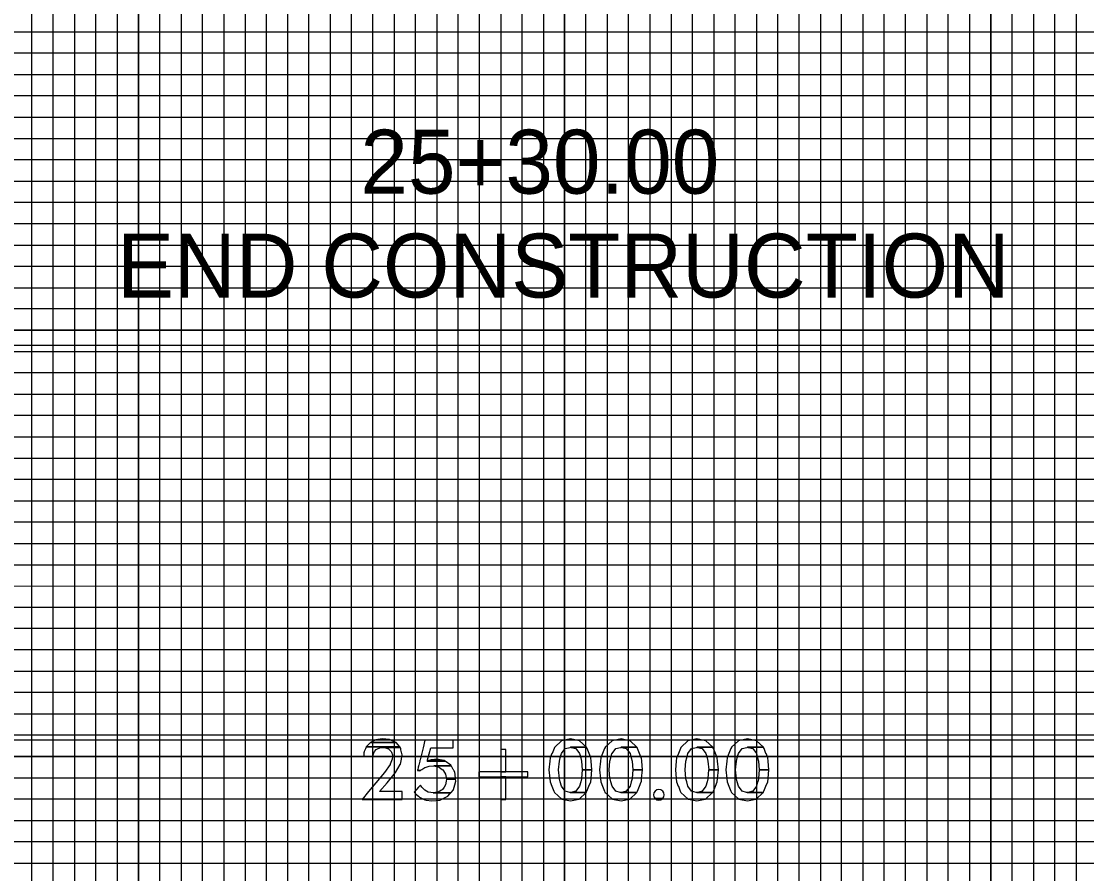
# Model space of a CAD drawing. Extents: x -13 to 323, y -5 to 1431.
# Drawn here: x 134.5 to 184.5, y 1164.5 to 1204.5 of the extents above; entities that cross this region are included whole.
import ezdxf

# ---------------------------------------------------------------- set-up
doc = ezdxf.new("R2010")
doc.units = 0
for name, color, linetype in [('Prop XS Station Labels', 7, 'Continuous'), ('Scratch_Level_3', 7, 'Continuous'), ('Scratch_Level_5', 7, 'Continuous'), ('Sheet Cross Section Grid Major CELL', 7, 'Continuous'), ('Sheet Cross Section Grid Middle CELL', 7, 'Continuous'), ('Sheet Cross Section Grid Minor 1 CELL', 7, 'Continuous'), ('Sheet Cross Section Grid Minor 2 CELL', 7, 'Continuous'), ('Sheet DOT Grid CELL', 7, 'Continuous')]:
    doc.layers.add(name, color=color, linetype=linetype)

msp = doc.modelspace()

# ---------------------------------------------------------------- linework, layer by layer
at = {"layer": 'Prop XS Station Labels'}
for points in [[(150.885, 1170.655), (150.69, 1170.447), (152.265, 1170.447), (152.085, 1170.655)], [(150.895, 1170.659), (150.885, 1170.655), (152.085, 1170.655), (152.082, 1170.659), (151.818, 1170.778), (151.786, 1170.793), (151.458, 1170.826), (151.458, 1170.826), (151.24, 1170.793), (151.144, 1170.778)], [(153.097, 1169.368), (153.092, 1169.345), (153.232, 1169.345), (153.259, 1169.368), (153.291, 1169.397), (153.433, 1169.483), (153.496, 1169.503), (153.636, 1169.546), (153.865, 1169.559), (154.681, 1169.559), (154.665, 1169.59), (154.396, 1169.78), (153.553, 1169.78), (153.56, 1169.806), (153.559, 1169.806), (153.57, 1169.845), (153.718, 1170.402), (154.769, 1170.402), (154.769, 1170.771), (153.443, 1170.771), (153.352, 1170.402), (153.215, 1169.845), (153.205, 1169.806), (153.199, 1169.78), (153.152, 1169.59), (153.145, 1169.559), (153.141, 1169.546), (153.13, 1169.503), (153.125, 1169.483), (153.105, 1169.397)], [(159.873, 1167.998), (160.272, 1167.916), (160.661, 1167.998), (160.683, 1168.003), (161.014, 1168.306), (160.265, 1168.306), (160.246, 1168.312), (160.236, 1168.315), (160.027, 1168.374), (159.853, 1168.6), (159.852, 1168.602), (159.852, 1168.602), (159.797, 1168.804), (159.796, 1168.807), (159.756, 1168.953), (159.754, 1168.962), (159.718, 1169.366), (159.718, 1169.371), (159.719, 1169.376), (159.754, 1169.779), (159.795, 1169.933), (159.796, 1169.937), (159.849, 1170.134), (159.851, 1170.14), (160.027, 1170.368), (160.253, 1170.427), (160.26, 1170.429), (160.281, 1170.435), (161.021, 1170.435), (160.695, 1170.734), (160.678, 1170.737), (160.276, 1170.826), (160.276, 1170.826), (159.86, 1170.737), (159.856, 1170.734), (159.533, 1170.435), (159.527, 1170.429), (159.525, 1170.427), (159.501, 1170.368), (159.407, 1170.14), (159.404, 1170.134), (159.324, 1169.937), (159.323, 1169.933), (159.307, 1169.779), (159.264, 1169.376), (159.264, 1169.371), (159.264, 1169.366), (159.305, 1168.962), (159.305, 1168.953), (159.32, 1168.807), (159.321, 1168.804), (159.403, 1168.602), (159.404, 1168.6), (159.496, 1168.374), (159.52, 1168.315), (159.522, 1168.312), (159.528, 1168.306), (159.867, 1168.003)], [(162.245, 1167.998), (162.645, 1167.916), (163.034, 1167.998), (163.055, 1168.003), (163.386, 1168.306), (162.638, 1168.306), (162.619, 1168.312), (162.609, 1168.315), (162.4, 1168.374), (162.225, 1168.6), (162.225, 1168.602), (162.225, 1168.602), (162.17, 1168.804), (162.169, 1168.807), (162.129, 1168.953), (162.126, 1168.962), (162.091, 1169.366), (162.091, 1169.371), (162.091, 1169.376), (162.126, 1169.779), (162.168, 1169.933), (162.169, 1169.937), (162.222, 1170.134), (162.224, 1170.14), (162.4, 1170.368), (162.625, 1170.427), (162.633, 1170.429), (162.654, 1170.435), (163.394, 1170.435), (163.067, 1170.734), (163.05, 1170.737), (162.649, 1170.826), (162.649, 1170.826), (162.233, 1170.737), (162.229, 1170.734), (161.906, 1170.435), (161.9, 1170.429), (161.898, 1170.427), (161.874, 1170.368), (161.78, 1170.14), (161.777, 1170.134), (161.696, 1169.937), (161.695, 1169.933), (161.68, 1169.779), (161.637, 1169.376), (161.636, 1169.371), (161.637, 1169.366), (161.677, 1168.962), (161.678, 1168.953), (161.693, 1168.807), (161.694, 1168.804), (161.776, 1168.602), (161.777, 1168.6), (161.869, 1168.374), (161.893, 1168.315), (161.895, 1168.312), (161.9, 1168.306), (162.24, 1168.003)], [(165.805, 1167.998), (166.204, 1167.916), (166.593, 1167.998), (166.615, 1168.003), (166.945, 1168.306), (166.197, 1168.306), (166.178, 1168.312), (166.168, 1168.315), (165.959, 1168.374), (165.785, 1168.6), (165.784, 1168.602), (165.784, 1168.602), (165.729, 1168.804), (165.728, 1168.807), (165.688, 1168.953), (165.685, 1168.962), (165.65, 1169.366), (165.65, 1169.371), (165.65, 1169.376), (165.685, 1169.779), (165.727, 1169.933), (165.728, 1169.937), (165.781, 1170.134), (165.783, 1170.14), (165.959, 1170.368), (166.185, 1170.427), (166.192, 1170.429), (166.213, 1170.435), (166.953, 1170.435), (166.626, 1170.734), (166.61, 1170.737), (166.208, 1170.826), (166.208, 1170.826), (165.792, 1170.737), (165.788, 1170.734), (165.465, 1170.435), (165.459, 1170.429), (165.457, 1170.427), (165.433, 1170.368), (165.339, 1170.14), (165.336, 1170.134), (165.255, 1169.937), (165.255, 1169.933), (165.239, 1169.779), (165.196, 1169.376), (165.195, 1169.371), (165.196, 1169.366), (165.236, 1168.962), (165.237, 1168.953), (165.252, 1168.807), (165.253, 1168.804), (165.335, 1168.602), (165.336, 1168.6), (165.428, 1168.374), (165.452, 1168.315), (165.454, 1168.312), (165.46, 1168.306), (165.799, 1168.003)], [(168.177, 1167.998), (168.576, 1167.916), (168.965, 1167.998), (168.987, 1168.003), (169.318, 1168.306), (168.57, 1168.306), (168.55, 1168.312), (168.541, 1168.315), (168.332, 1168.374), (168.157, 1168.6), (168.157, 1168.602), (168.156, 1168.602), (168.101, 1168.804), (168.1, 1168.807), (168.06, 1168.953), (168.058, 1168.962), (168.023, 1169.366), (168.023, 1169.371), (168.023, 1169.376), (168.058, 1169.779), (168.1, 1169.933), (168.1, 1169.937), (168.154, 1170.134), (168.155, 1170.14), (168.332, 1170.368), (168.557, 1170.427), (168.565, 1170.429), (168.585, 1170.435), (169.325, 1170.435), (168.999, 1170.734), (168.982, 1170.737), (168.581, 1170.826), (168.58, 1170.826), (168.165, 1170.737), (168.16, 1170.734), (167.838, 1170.435), (167.832, 1170.429), (167.83, 1170.427), (167.805, 1170.368), (167.711, 1170.14), (167.709, 1170.134), (167.628, 1169.937), (167.627, 1169.933), (167.611, 1169.779), (167.569, 1169.376), (167.568, 1169.371), (167.569, 1169.366), (167.609, 1168.962), (167.61, 1168.953), (167.625, 1168.807), (167.625, 1168.804), (167.708, 1168.602), (167.709, 1168.6), (167.801, 1168.374), (167.825, 1168.315), (167.826, 1168.312), (167.832, 1168.306), (168.172, 1168.003)], [(150.8, 1168.353), (150.496, 1167.989), (152.376, 1167.989), (152.376, 1168.353), (151.308, 1168.353), (151.667, 1168.766), (152.06, 1169.246), (152.065, 1169.251), (152.287, 1169.626), (152.286, 1169.626), (152.293, 1169.636), (152.34, 1169.876), (152.365, 1169.997), (152.375, 1170.047), (152.37, 1170.069), (152.369, 1170.075), (152.343, 1170.196), (152.34, 1170.208), (152.335, 1170.23), (152.314, 1170.332), (152.314, 1170.332), (152.308, 1170.359), (152.297, 1170.411), (152.292, 1170.416), (152.285, 1170.425), (151.548, 1170.425), (151.571, 1170.416), (151.587, 1170.411), (151.736, 1170.359), (151.763, 1170.332), (151.863, 1170.23), (151.87, 1170.208), (151.874, 1170.196), (151.915, 1170.075), (151.915, 1170.069), (151.915, 1170.047), (151.914, 1169.997), (151.912, 1169.876), (151.817, 1169.636), (151.814, 1169.626), (151.549, 1169.251), (151.545, 1169.246), (151.144, 1168.766)], [(150.569, 1170.047), (150.565, 1169.997), (151.004, 1169.997), (151.008, 1170.047), (151.01, 1170.069), (151.012, 1170.075), (151.056, 1170.196), (151.065, 1170.208), (151.082, 1170.23), (151.161, 1170.332), (151.215, 1170.359), (151.32, 1170.411), (151.331, 1170.416), (151.548, 1170.425), (152.285, 1170.425), (152.265, 1170.447), (150.69, 1170.447), (150.68, 1170.425), (150.676, 1170.416), (150.674, 1170.411), (150.65, 1170.359), (150.639, 1170.332), (150.593, 1170.23), (150.584, 1170.208), (150.582, 1170.196), (150.571, 1170.075), (150.571, 1170.069)], [(157.009, 1170.331), (157.009, 1169.274), (157.236, 1169.274), (157.236, 1170.331)], [(160.795, 1169.779), (160.827, 1169.376), (161.281, 1169.376), (161.242, 1169.779), (161.227, 1169.933), (161.225, 1169.937), (161.225, 1169.937), (161.146, 1170.134), (161.146, 1170.134), (161.144, 1170.14), (161.052, 1170.368), (161.051, 1170.368), (161.028, 1170.427), (161.027, 1170.429), (161.021, 1170.435), (160.281, 1170.435), (160.3, 1170.429), (160.307, 1170.427), (160.52, 1170.368), (160.695, 1170.14), (160.7, 1170.134), (160.752, 1169.937), (160.753, 1169.933)], [(163.167, 1169.779), (163.2, 1169.376), (163.654, 1169.376), (163.615, 1169.779), (163.6, 1169.933), (163.598, 1169.937), (163.598, 1169.937), (163.519, 1170.134), (163.519, 1170.134), (163.516, 1170.14), (163.425, 1170.368), (163.424, 1170.368), (163.4, 1170.427), (163.4, 1170.429), (163.394, 1170.435), (162.654, 1170.435), (162.673, 1170.429), (162.68, 1170.427), (162.893, 1170.368), (163.068, 1170.14), (163.073, 1170.134), (163.125, 1169.937), (163.126, 1169.933)], [(166.726, 1169.779), (166.759, 1169.376), (167.213, 1169.376), (167.174, 1169.779), (167.159, 1169.933), (167.157, 1169.937), (167.157, 1169.937), (167.078, 1170.134), (167.078, 1170.134), (167.075, 1170.14), (166.984, 1170.368), (166.983, 1170.368), (166.96, 1170.427), (166.959, 1170.429), (166.953, 1170.435), (166.213, 1170.435), (166.232, 1170.429), (166.239, 1170.427), (166.452, 1170.368), (166.627, 1170.14), (166.632, 1170.134), (166.684, 1169.937), (166.685, 1169.933)], [(169.099, 1169.779), (169.132, 1169.376), (169.586, 1169.376), (169.546, 1169.779), (169.532, 1169.933), (169.53, 1169.937), (169.53, 1169.937), (169.451, 1170.134), (169.45, 1170.134), (169.448, 1170.14), (169.356, 1170.368), (169.356, 1170.368), (169.332, 1170.427), (169.332, 1170.429), (169.325, 1170.435), (168.585, 1170.435), (168.605, 1170.429), (168.611, 1170.427), (168.825, 1170.368), (169, 1170.14), (169.005, 1170.134), (169.057, 1169.937), (169.058, 1169.933)], [(153.628, 1169.806), (153.553, 1169.78), (154.396, 1169.78), (154.36, 1169.806), (154.165, 1169.845), (153.743, 1169.845)], [(154.019, 1169.874), (153.744, 1169.845), (154.164, 1169.845), (154.019, 1169.874)], [(154.409, 1169.171), (154.454, 1168.931), (154.879, 1168.931), (154.857, 1169.171), (154.857, 1169.171), (154.85, 1169.252), (154.811, 1169.322), (154.799, 1169.345), (154.786, 1169.368), (154.77, 1169.397), (154.723, 1169.483), (154.712, 1169.503), (154.688, 1169.546), (154.681, 1169.559), (153.865, 1169.559), (153.918, 1169.546), (154.1, 1169.503), (154.128, 1169.483), (154.25, 1169.397), (154.291, 1169.368), (154.305, 1169.345), (154.319, 1169.322), (154.36, 1169.252)], [(153.091, 1169.345), (153.207, 1169.322), (153.232, 1169.345)], [(155.974, 1169.274), (155.974, 1169.046), (158.272, 1169.046), (158.272, 1169.274)], [(157.009, 1169.046), (157.009, 1167.989), (157.236, 1167.989), (157.236, 1169.046)], [(160.286, 1168.312), (160.265, 1168.306), (161.014, 1168.306), (161.02, 1168.312), (161.023, 1168.315), (161.047, 1168.374), (161.14, 1168.6), (161.141, 1168.602), (161.225, 1168.804), (161.226, 1168.807), (161.24, 1168.953), (161.241, 1168.962), (161.281, 1169.366), (161.282, 1169.371), (161.281, 1169.376), (160.827, 1169.376), (160.827, 1169.371), (160.826, 1169.366), (160.794, 1168.962), (160.794, 1168.953), (160.754, 1168.807), (160.753, 1168.804), (160.699, 1168.602), (160.697, 1168.6), (160.52, 1168.374), (160.296, 1168.315)], [(162.659, 1168.312), (162.638, 1168.306), (163.386, 1168.306), (163.392, 1168.312), (163.395, 1168.315), (163.42, 1168.374), (163.513, 1168.6), (163.514, 1168.602), (163.597, 1168.804), (163.599, 1168.807), (163.613, 1168.953), (163.614, 1168.962), (163.654, 1169.366), (163.655, 1169.371), (163.654, 1169.376), (163.2, 1169.376), (163.2, 1169.371), (163.199, 1169.366), (163.167, 1168.962), (163.166, 1168.953), (163.127, 1168.807), (163.126, 1168.804), (163.072, 1168.602), (163.07, 1168.6), (162.893, 1168.374), (162.669, 1168.315)], [(166.218, 1168.312), (166.197, 1168.306), (166.945, 1168.306), (166.951, 1168.312), (166.955, 1168.315), (166.979, 1168.374), (167.072, 1168.6), (167.073, 1168.602), (167.156, 1168.804), (167.158, 1168.807), (167.172, 1168.953), (167.173, 1168.962), (167.213, 1169.366), (167.214, 1169.371), (167.213, 1169.376), (166.759, 1169.376), (166.759, 1169.371), (166.758, 1169.366), (166.726, 1168.962), (166.725, 1168.953), (166.686, 1168.807), (166.685, 1168.804), (166.631, 1168.602), (166.629, 1168.6), (166.452, 1168.374), (166.228, 1168.315)], [(168.59, 1168.312), (168.57, 1168.306), (169.318, 1168.306), (169.324, 1168.312), (169.327, 1168.315), (169.351, 1168.374), (169.445, 1168.6), (169.446, 1168.602), (169.529, 1168.804), (169.531, 1168.807), (169.545, 1168.953), (169.546, 1168.962), (169.586, 1169.366), (169.586, 1169.371), (169.586, 1169.376), (169.131, 1169.376), (169.131, 1169.371), (169.131, 1169.366), (169.099, 1168.962), (169.098, 1168.953), (169.059, 1168.807), (169.058, 1168.804), (169.004, 1168.602), (169.002, 1168.6), (168.825, 1168.374), (168.601, 1168.315)], [(153.495, 1167.956), (153.766, 1167.916), (154.162, 1167.956), (154.179, 1167.964), (154.425, 1168.084), (154.425, 1168.084), (154.525, 1168.132), (154.613, 1168.24), (154.652, 1168.287), (153.829, 1168.287), (153.61, 1168.326), (153.606, 1168.327), (153.601, 1168.33), (153.435, 1168.422), (153.415, 1168.443), (153.404, 1168.455), (153.403, 1168.455), (153.302, 1168.559), (153.237, 1168.66), (153.237, 1168.66), (153.146, 1168.559), (153.052, 1168.455), (153.041, 1168.443), (153.022, 1168.422), (152.94, 1168.33), (152.937, 1168.327), (152.939, 1168.326), (152.969, 1168.287), (153.007, 1168.24), (153.134, 1168.132), (153.191, 1168.084), (153.439, 1167.964)], [(154.043, 1168.326), (153.829, 1168.287), (154.652, 1168.287), (154.683, 1168.326), (154.685, 1168.327), (154.687, 1168.33), (154.686, 1168.33), (154.762, 1168.422), (154.779, 1168.443), (154.782, 1168.455), (154.811, 1168.559), (154.841, 1168.669), (154.887, 1168.836), (154.879, 1168.931), (154.453, 1168.931), (154.437, 1168.836), (154.408, 1168.669), (154.338, 1168.559), (154.271, 1168.455), (154.251, 1168.443), (154.218, 1168.422), (154.069, 1168.33), (154.054, 1168.327)], [(164.193, 1168.107), (164.247, 1168.026), (164.603, 1168.026), (164.656, 1168.107), (164.675, 1168.203), (164.656, 1168.299), (164.603, 1168.38), (164.521, 1168.434), (164.425, 1168.453), (164.328, 1168.434), (164.247, 1168.38), (164.193, 1168.299), (164.174, 1168.203)], [(164.328, 1167.971), (164.425, 1167.953), (164.521, 1167.971), (164.603, 1168.026), (164.247, 1168.026)]]:
    msp.add_lwpolyline(points, close=True, dxfattribs=at)
at = {"layer": 'Scratch_Level_3'}
msp.add_lwpolyline([(20, 1189.301), (300, 1189.301), (300, 1170.769), (20, 1170.769)], close=True, dxfattribs=at)
at = {"layer": 'Scratch_Level_5'}
msp.add_line((160, 1100), (160, 1430.809), dxfattribs=at)
at = {"layer": 'Sheet Cross Section Grid Major CELL'}
for p, q in [((140, 1310), (140, 1100)), ((150, 1100), (150, 1310)), ((160, 1310), (160, 1100)), ((170, 1100), (170, 1310)), ((180, 1310), (180, 1100))]:
    msp.add_line(p, q, dxfattribs=at)
for points in [[(0, 1200), (320, 1200), (320, 1190), (0, 1190)], [(0, 1180), (320, 1180), (320, 1170), (0, 1170)]]:
    msp.add_lwpolyline(points, dxfattribs=at)
at = {"layer": 'Sheet Cross Section Grid Middle CELL'}
for points in [[(125, 1100), (135, 1100), (135, 1310)], [(145, 1310), (145, 1100), (155, 1100), (155, 1310)], [(165, 1310), (165, 1100), (175, 1100), (175, 1310)], [(0, 1185), (320, 1185), (320, 1195), (0, 1195)], [(0, 1165), (320, 1165), (320, 1175), (0, 1175)]]:
    msp.add_lwpolyline(points, dxfattribs=at)
at = {"layer": 'Sheet Cross Section Grid Minor 1 CELL'}
for points in [[(0, 1204), (320, 1204), (320, 1203), (0, 1203)], [(0, 1202), (320, 1202), (320, 1201), (0, 1201)], [(0, 1199), (320, 1199), (320, 1198), (0, 1198)], [(0, 1197), (320, 1197), (320, 1196), (0, 1196)], [(0, 1194), (320, 1194), (320, 1193), (0, 1193)], [(0, 1192), (320, 1192), (320, 1191), (0, 1191)], [(0, 1189), (320, 1189), (320, 1188), (0, 1188)], [(0, 1187), (320, 1187), (320, 1186), (0, 1186)], [(0, 1184), (320, 1184), (320, 1183), (0, 1183)], [(0, 1182), (320, 1182), (320, 1181), (0, 1181)], [(0, 1179), (320, 1179), (319.99, 1177.98), (0, 1178)], [(0, 1177), (320, 1177), (320, 1176), (0, 1176)], [(0, 1174), (320, 1174), (320, 1173), (0, 1173)], [(0, 1172), (320, 1172), (320, 1171), (0, 1171)], [(0, 1169), (320, 1169), (320, 1168), (0, 1168)], [(0, 1167), (320, 1167), (320, 1166), (0, 1166)]]:
    msp.add_lwpolyline(points, dxfattribs=at)
at = {"layer": 'Sheet Cross Section Grid Minor 2 CELL'}
for points in [[(135, 1100), (136, 1100), (136, 1310), (137, 1310), (137, 1100)], [(137, 1100), (138, 1100), (138, 1310), (139, 1310), (139, 1100)], [(140, 1100), (141, 1100), (141, 1310), (142, 1310), (142, 1100)], [(142, 1100), (143, 1100), (143, 1310), (144, 1310), (144, 1100)], [(145, 1100), (146, 1100), (146, 1310), (147, 1310), (147, 1100)], [(147, 1100), (148, 1100), (148, 1310), (149, 1310), (149, 1100)], [(150, 1100), (151, 1100), (151, 1310), (152, 1310), (152, 1100)], [(152, 1100), (153, 1100), (153, 1310), (154, 1310), (154, 1100)], [(155, 1100), (156, 1100), (156, 1310), (157, 1310), (157, 1100)], [(157, 1100), (158, 1100), (158, 1310), (159, 1310), (159, 1100)], [(160, 1100), (161, 1100), (161, 1310), (162, 1310), (162, 1100)], [(162, 1100), (163, 1100), (163, 1310), (164, 1310), (164, 1100)], [(165, 1100), (166, 1100), (166, 1310), (167, 1310), (167, 1100)], [(167, 1100), (168, 1100), (168, 1310), (169, 1310), (169, 1100)], [(170, 1100), (171, 1100), (171, 1310), (172, 1310), (172, 1100)], [(172, 1100), (173, 1100), (173, 1310), (174, 1310), (174, 1100)], [(175, 1100), (176, 1100), (176, 1310), (177, 1310), (177, 1100)], [(177, 1100), (178, 1100), (178, 1310), (179, 1310), (179, 1100)], [(180, 1100), (181, 1100), (181, 1310), (182, 1310), (182, 1100)], [(182, 1100), (183, 1100), (183, 1310), (184, 1310), (184, 1100)]]:
    msp.add_lwpolyline(points, dxfattribs=at)
at = {"layer": 'Sheet DOT Grid CELL'}
for p, q in [((140, 1100), (140, 1310)), ((150, 1100), (150, 1310)), ((160, 1100), (160, 1310)), ((170, 1100), (170, 1310)), ((180, 1100), (180, 1310)), ((0, 1200), (320, 1200)), ((0, 1190), (320, 1190)), ((0, 1180), (320, 1180)), ((0, 1170), (320, 1170))]:
    msp.add_line(p, q, dxfattribs=at)

# ---------------------------------------------------------------- texts
at = {"layer": 'Prop XS Station Labels'}
for s, p in [('25+30.00', (150.414, 1196.412)), ('END CONSTRUCTION', (138.991, 1191.537))]:
    msp.add_text(s, height=3, dxfattribs=at).set_placement(p)

doc.saveas('drawing.dxf')
